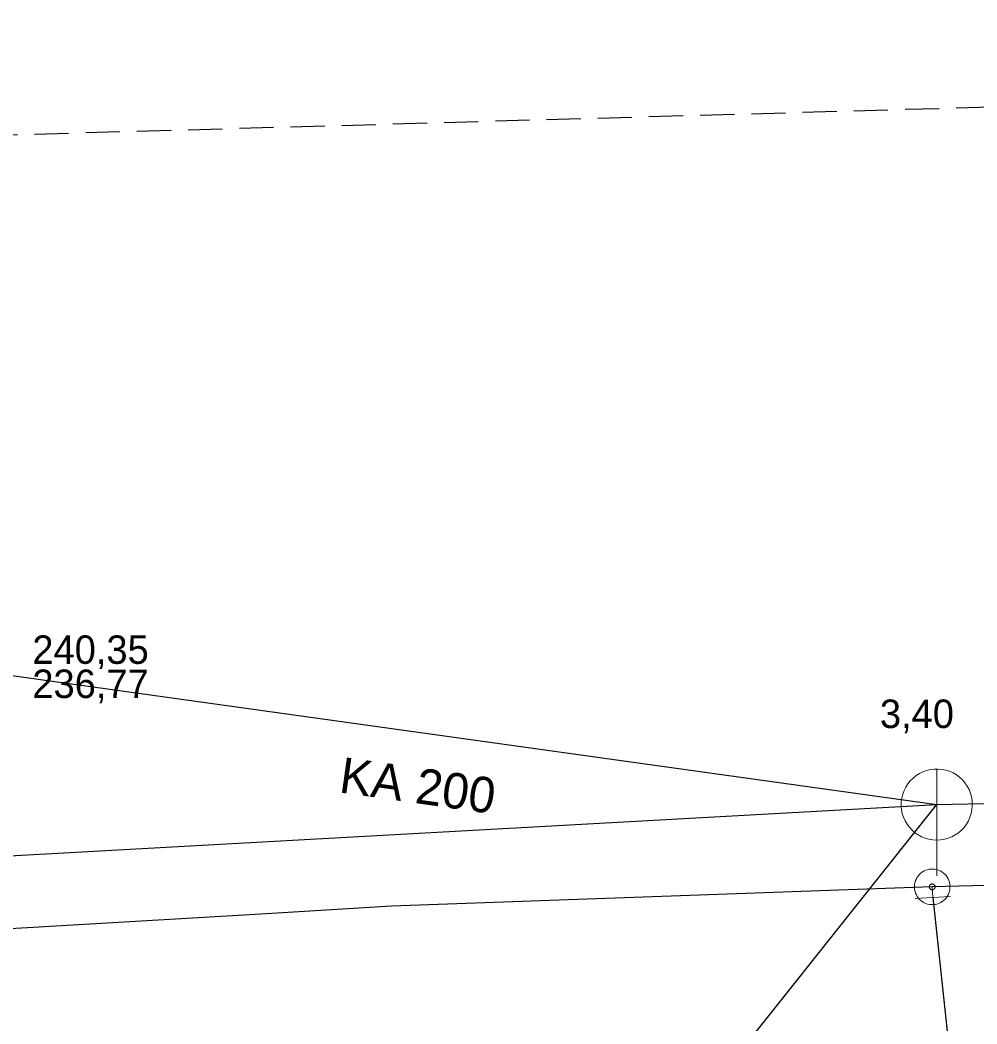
# Model space of a CAD drawing. Extents: x -777996 to -777727, y -976581 to -976199.
# Drawn here: x -777961.28 to -777934.38, y -976227.07 to -976198.85 of the extents above; entities that cross this region are included whole.
import ezdxf

# ---------------------------------------------------------------- set-up
doc = ezdxf.new("R2010")
doc.units = 0
doc.header["$LTSCALE"] = 0.32
doc.linetypes.add('MEDIUM_DASHED', pattern=[4.5, 3, -1.5])
for name, color, linetype, lineweight in [('1', 7, 'MEDIUM_DASHED', 25), ('14', 7, 'Continuous', 25), ('17', 7, 'Continuous', 25), ('22', 7, 'Continuous', 13), ('34', 7, 'Continuous', 13), ('47', 7, 'Continuous', 13)]:
    doc.layers.add(name, color=color, linetype=linetype, lineweight=lineweight)

msp = doc.modelspace()

# ---------------------------------------------------------------- linework, layer by layer
at = {"layer": '1'}
msp.add_lwpolyline([(-777995.417, -976203.033), (-777848.18, -976198.846), (-777864.927, -976230.247), (-777726.762, -976491.225), (-777789.565, -976581.242), (-777941.686, -976558.215), (-777989.136, -976405.396)], close=True, dxfattribs=at)
at = {"layer": '14'}
for p, q in [((-777962.675, -976217.105), (-777935.509, -976220.899)), ((-777935.509, -976220.899), (-777918.245, -976220.55)), ((-777994.761, -976224.174), (-777935.509, -976220.899)), ((-777946.791, -976235.083), (-777935.509, -976220.899))]:
    msp.add_line(p, q, dxfattribs=at)
at = {"layer": '14', "lineweight": 13}
msp.add_line((-777935.619, -976223.512), (-777935.637, -976223.213), dxfattribs=at)
at = {"layer": '17'}
for p, q in [((-777930.877, -976223.09), (-777935.637, -976223.213)), ((-777935.619, -976223.512), (-777934.804, -976231.131))]:
    msp.add_line(p, q, dxfattribs=at)
msp.add_lwpolyline([(-777935.637, -976223.213), (-777950.839, -976223.756), (-777954.513, -976223.98), (-777963.963, -976224.532), (-777968.897, -976224.76), (-777972.243, -976224.917), (-777988.739, -976225.824), (-777994.698, -976226.192)], dxfattribs=at)
at = {"layer": '22'}
msp.add_line((-777935.509, -976222.899), (-777935.508, -976219.899), dxfattribs=at)
msp.add_lwpolyline([(-777934.509, -976220.899), (-777934.514, -976220.79), (-777934.532, -976220.682), (-777934.562, -976220.576), (-777934.602, -976220.475), (-777934.654, -976220.378), (-777934.716, -976220.288), (-777934.788, -976220.205), (-777934.868, -976220.131), (-777934.956, -976220.065), (-777935.05, -976220.01), (-777935.15, -976219.965), (-777935.255, -976219.932), (-777935.362, -976219.91), (-777935.471, -976219.9), (-777935.581, -976219.902), (-777935.689, -976219.916), (-777935.796, -976219.941), (-777935.899, -976219.978), (-777935.997, -976220.027), (-777936.089, -976220.085), (-777936.175, -976220.154), (-777936.252, -976220.231), (-777936.321, -976220.317), (-777936.38, -976220.409), (-777936.428, -976220.507), (-777936.465, -976220.61), (-777936.491, -976220.717), (-777936.505, -976220.825), (-777936.508, -976220.935), (-777936.498, -976221.044), (-777936.477, -976221.151), (-777936.443, -976221.255), (-777936.399, -976221.355), (-777936.344, -976221.45), (-777936.278, -976221.538), (-777936.204, -976221.618), (-777936.121, -976221.69), (-777936.031, -976221.752), (-777935.935, -976221.804), (-777935.833, -976221.845), (-777935.728, -976221.875), (-777935.62, -976221.893), (-777935.51, -976221.899), (-777935.401, -976221.893), (-777935.293, -976221.875), (-777935.188, -976221.846), (-777935.086, -976221.805), (-777934.989, -976221.753), (-777934.899, -976221.691), (-777934.816, -976221.62), (-777934.741, -976221.54), (-777934.676, -976221.452), (-777934.62, -976221.358), (-777934.576, -976221.258), (-777934.542, -976221.154), (-777934.52, -976221.046), (-777934.51, -976220.937)], close=True, dxfattribs=at)
at = {"layer": '34'}
msp.add_line((-777935.119, -976223.482), (-777936.118, -976223.54), dxfattribs=at)
at = {"layer": '47'}
for points in [[(-777935.137, -976223.186), (-777935.143, -976223.134), (-777935.154, -976223.082), (-777935.17, -976223.033), (-777935.191, -976222.985), (-777935.218, -976222.94), (-777935.249, -976222.897), (-777935.284, -976222.859), (-777935.323, -976222.824), (-777935.365, -976222.793), (-777935.41, -976222.767), (-777935.458, -976222.745), (-777935.508, -976222.73), (-777935.559, -976222.719), (-777935.611, -976222.713), (-777935.663, -976222.713), (-777935.715, -976222.719), (-777935.767, -976222.73), (-777935.817, -976222.747), (-777935.864, -976222.767), (-777935.909, -976222.794), (-777935.952, -976222.825), (-777935.991, -976222.86), (-777936.026, -976222.899), (-777936.057, -976222.941), (-777936.082, -976222.986), (-777936.104, -976223.034), (-777936.12, -976223.084), (-777936.13, -976223.135), (-777936.136, -976223.187), (-777936.136, -976223.239), (-777936.13, -976223.291), (-777936.119, -976223.343), (-777936.103, -976223.393), (-777936.082, -976223.44), (-777936.055, -976223.485), (-777936.025, -976223.528), (-777935.99, -976223.567), (-777935.951, -976223.602), (-777935.908, -976223.633), (-777935.863, -976223.658), (-777935.815, -976223.68), (-777935.766, -976223.696), (-777935.714, -976223.706), (-777935.662, -976223.712), (-777935.61, -976223.712), (-777935.558, -976223.706), (-777935.506, -976223.695), (-777935.457, -976223.68), (-777935.409, -976223.658), (-777935.364, -976223.631), (-777935.321, -976223.601), (-777935.283, -976223.566), (-777935.248, -976223.527), (-777935.217, -976223.484), (-777935.191, -976223.439), (-777935.169, -976223.391), (-777935.154, -976223.342), (-777935.143, -976223.29), (-777935.137, -976223.238)], [(-777935.555, -976223.208), (-777935.555, -976223.199), (-777935.558, -976223.191), (-777935.56, -976223.183), (-777935.563, -976223.176), (-777935.568, -976223.168), (-777935.573, -976223.161), (-777935.579, -976223.154), (-777935.585, -976223.149), (-777935.592, -976223.144), (-777935.599, -976223.139), (-777935.608, -976223.136), (-777935.616, -976223.133), (-777935.624, -976223.132), (-777935.632, -976223.13), (-777935.641, -976223.131), (-777935.65, -976223.131), (-777935.658, -976223.134), (-777935.666, -976223.136), (-777935.673, -976223.139), (-777935.681, -976223.144), (-777935.688, -976223.149), (-777935.695, -976223.155), (-777935.7, -976223.161), (-777935.706, -976223.168), (-777935.71, -976223.175), (-777935.713, -976223.184), (-777935.716, -976223.192), (-777935.717, -976223.2), (-777935.719, -976223.208), (-777935.718, -976223.217), (-777935.718, -976223.226), (-777935.715, -976223.234), (-777935.713, -976223.242), (-777935.71, -976223.249), (-777935.705, -976223.257), (-777935.701, -976223.264), (-777935.694, -976223.271), (-777935.688, -976223.276), (-777935.681, -976223.282), (-777935.674, -976223.286), (-777935.665, -976223.289), (-777935.657, -976223.292), (-777935.649, -976223.293), (-777935.641, -976223.295), (-777935.632, -976223.294), (-777935.623, -976223.294), (-777935.615, -976223.291), (-777935.607, -976223.289), (-777935.6, -976223.286), (-777935.592, -976223.281), (-777935.585, -976223.277), (-777935.578, -976223.27), (-777935.573, -976223.264), (-777935.568, -976223.257), (-777935.563, -976223.25), (-777935.56, -976223.241), (-777935.557, -976223.233), (-777935.556, -976223.225), (-777935.554, -976223.217)]]:
    msp.add_lwpolyline(points, close=True, dxfattribs=at)

# ---------------------------------------------------------------- texts
at = {"layer": '1'}
msp.add_text('3,40', height=0.8, dxfattribs=at).set_placement((-777937.108, -976218.747))
msp.add_text('KA 200', height=1, rotation=352, dxfattribs=at).set_placement((-777952.337, -976220.553))
at = {"layer": '22'}
for s, p in [('240,35', (-777960.932, -976216.944)), ('236,77', (-777960.932, -976217.904))]:
    msp.add_text(s, height=0.8, dxfattribs=at).set_placement(p)

doc.saveas('drawing.dxf')
